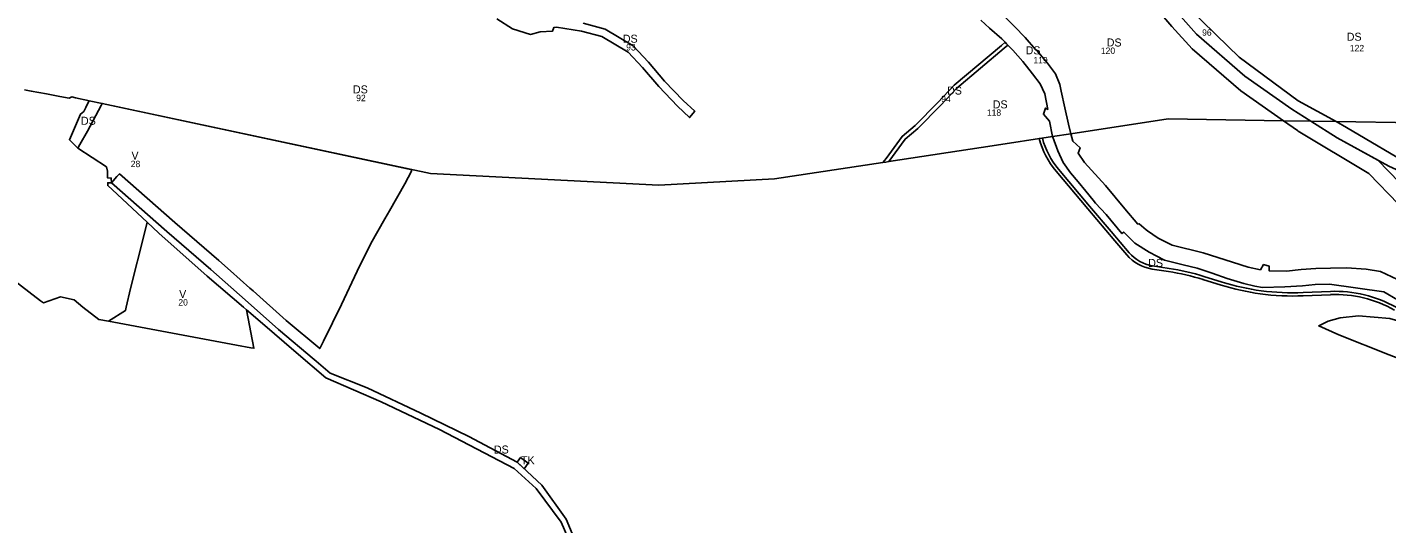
# Model space of a CAD drawing. Extents: x -521621 to -516769, y -1190068 to -1185078.
# Drawn here: x -519528 to -517829, y -1188202 to -1187582 of the extents above; entities that cross this region are included whole.
import ezdxf

# ---------------------------------------------------------------- set-up
doc = ezdxf.new("R2010")
doc.units = 0
for name, color, linetype in [('fpl_id', 7, 'Continuous'), ('v_infrastr_n', 7, 'Continuous'), ('v_infrastr_s', 7, 'Continuous'), ('voda_n', 7, 'Continuous'), ('voda_s', 7, 'Continuous'), ('vyroba_n', 7, 'Continuous'), ('vyroba_s', 7, 'Continuous')]:
    doc.layers.add(name, color=color, linetype=linetype)

msp = doc.modelspace()

# ---------------------------------------------------------------- linework, layer by layer
at = {"layer": 'v_infrastr_n'}
for points in [[(-518142.6, -1187500), (-518125.5, -1187497.4), (-518080.2, -1187553.9), (-518042.1, -1187591.1), (-518013.4, -1187619.1), (-517939.8, -1187673.3), (-517892.4, -1187699.4), (-517923.8, -1187698.9), (-517947.8, -1187683.7), (-518006.3, -1187642.7), (-518067, -1187590.4), (-518102.9, -1187549.4), (-518111.5, -1187538.9), (-518137.5, -1187507.1)], [(-518311.5, -1187525.7), (-518193.2, -1187507.7), (-518188.5, -1187512.3), (-518115.1, -1187560.4), (-518097.5, -1187580.5), (-518072.1, -1187608.7), (-518011.3, -1187661), (-517958.1, -1187698.4), (-518102, -1187696.1), (-518223.7, -1187714.7), (-518226.7, -1187702.5), (-518231.2, -1187682.4), (-518235.9, -1187661.6), (-518237.5, -1187652.9), (-518243.1, -1187639.9), (-518253.1, -1187626.6), (-518266.5, -1187610.8), (-518267.8, -1187609.4), (-518281, -1187594.4), (-518294.1, -1187580.8), (-518310.4, -1187564.3), (-518318.7, -1187557.1), (-518326.5, -1187550.1)], [(-518193.2, -1187507.7), (-518165.5, -1187503.5), (-518111.5, -1187538.9), (-518102.9, -1187549.4), (-518067, -1187590.4), (-518006.3, -1187642.7), (-517947.8, -1187683.7), (-517923.8, -1187698.9), (-517958.1, -1187698.4), (-518011.3, -1187661), (-518072.1, -1187608.7), (-518097.5, -1187580.5), (-518115.1, -1187560.4), (-518188.5, -1187512.3)], [(-518434.6, -1187717.9), (-518418.1, -1187704.4), (-518390.1, -1187675.7), (-518369.6, -1187653.8), (-518310.5, -1187604.3), (-518305.9, -1187600.4), (-518304.1, -1187602.2), (-518302.4, -1187604), (-518307, -1187607.8), (-518366.2, -1187657.5), (-518386.5, -1187679.2), (-518414.8, -1187708.1), (-518430.9, -1187721.3), (-518451.1, -1187749.3), (-518454.9, -1187749.9), (-518458.6, -1187750.5), (-518454.6, -1187745.7), (-518434.6, -1187718)]]:
    msp.add_lwpolyline(points, close=True, dxfattribs=at)
for points in [[(-518125.5, -1187497.4), (-518115.5, -1187495.9), (-517932.8, -1187498.8), (-517912.3, -1187500.7), (-517903.3, -1187502.1), (-517892, -1187510.1), (-517869.1, -1187523.4), (-517829, -1187538.4), (-517785.5, -1187554.6), (-517780, -1187556.7), (-517749.3, -1187570.2), (-517671.4, -1187605.2), (-517631.2, -1187635), (-517621, -1187653.2), (-517598.9, -1187661.5), (-517592.8, -1187665.3), (-517589.2, -1187666.9), (-517596.1, -1187704.1), (-517892.4, -1187699.4)], [(-517892.4, -1187699.4), (-517939.8, -1187673.3), (-518013.4, -1187619.1), (-518042.1, -1187591.1), (-518080.2, -1187553.9), (-518125.5, -1187497.4)], [(-518336.4, -1187572.9), (-518325.6, -1187582.7), (-518310, -1187596), (-518305.9, -1187600.4), (-518310.5, -1187604.3), (-518369.6, -1187653.8), (-518390.1, -1187675.7), (-518418.1, -1187704.4), (-518434.6, -1187717.9), (-518454.6, -1187745.7), (-518458.6, -1187750.5), (-518594.2, -1187771.1), (-518738.7, -1187779), (-519023.8, -1187764.4), (-519433.9, -1187676.7), (-519450.5, -1187673.5), (-519453.5, -1187672.8), (-519458, -1187671.8), (-519461.7, -1187670.9), (-519467.2, -1187669.7), (-519472.1, -1187668.6), (-519475.5, -1187670.1), (-519486.8, -1187668), (-519495.4, -1187666.4), (-519503.6, -1187664.9), (-519513.2, -1187663.1), (-519522.7, -1187661.3), (-519531.3, -1187659.7)], [(-518833.1, -1187576.5), (-518805.7, -1187584), (-518770.6, -1187604.7), (-518751.6, -1187625.3), (-518731.3, -1187649), (-518708, -1187673), (-518693.8, -1187686.5), (-518700.2, -1187694.3), (-518715.1, -1187680.2), (-518738.7, -1187655.7), (-518759, -1187631.9), (-518777, -1187612.5), (-518809.6, -1187593.3), (-518835.2, -1187586.3), (-518866.3, -1187581.6), (-518869.6, -1187581.7), (-518871.3, -1187586.4), (-518887, -1187587.1), (-518898.8, -1187590.5), (-518921.5, -1187583.6), (-518941, -1187571)], [(-518941, -1187571), (-518921.5, -1187583.6), (-518898.8, -1187590.5), (-518887, -1187587.1), (-518871.3, -1187586.4), (-518869.6, -1187581.7), (-518866.3, -1187581.6), (-518835.2, -1187586.3), (-518809.6, -1187593.3), (-518777, -1187612.5), (-518759, -1187631.9), (-518738.7, -1187655.7), (-518715.1, -1187680.2), (-518700.2, -1187694.3), (-518693.8, -1187686.5), (-518708, -1187673), (-518731.3, -1187649), (-518751.6, -1187625.3), (-518770.6, -1187604.7), (-518805.7, -1187584), (-518833.1, -1187576.5)], [(-518294.1, -1187580.8), (-518281, -1187594.4), (-518267.8, -1187609.4), (-518266.5, -1187610.8), (-518253.1, -1187626.6), (-518243.1, -1187639.9), (-518237.5, -1187652.9), (-518235.9, -1187661.6), (-518231.2, -1187682.4), (-518226.7, -1187702.5), (-518223.7, -1187714.7), (-518246.6, -1187718.2), (-518250.4, -1187698.8), (-518258, -1187690.3), (-518255.4, -1187682.6), (-518252.6, -1187684.1), (-518256.3, -1187664.8), (-518262.3, -1187652.3), (-518271.6, -1187639.8), (-518283.6, -1187624.5), (-518296.4, -1187610.4), (-518302.4, -1187604), (-518304.1, -1187602.2), (-518305.9, -1187600.4), (-518310, -1187596), (-518325.6, -1187582.7), (-518336.4, -1187572.9)], [(-518246.6, -1187718.2), (-518322.2, -1187729.7), (-518451.1, -1187749.3), (-518430.9, -1187721.3), (-518414.8, -1187708.1), (-518386.5, -1187679.2), (-518366.2, -1187657.5), (-518307, -1187607.8), (-518302.4, -1187604)], [(-518302.4, -1187604), (-518296.4, -1187610.4), (-518283.6, -1187624.5), (-518271.6, -1187639.8), (-518262.3, -1187652.3), (-518256.3, -1187664.8), (-518252.6, -1187684.1), (-518255.4, -1187682.6), (-518258, -1187690.3), (-518250.4, -1187698.8), (-518246.6, -1187718.2)], [(-517940.8, -1187710.5), (-517958.1, -1187698.4), (-517923.8, -1187698.9), (-517890.9, -1187719.9), (-517840.1, -1187747.4)], [(-517840.1, -1187747.4), (-517799.3, -1187789.7), (-517714, -1187904.5), (-517695.5, -1187912.6), (-517704.3, -1187930.6), (-517726.9, -1187920.7), (-517814.6, -1187802.6), (-517851.6, -1187764.3), (-517939.7, -1187711.3)]]:
    msp.add_lwpolyline(points, dxfattribs=at)
msp.add_arc((-517929.3, -1187694.1), 20, 234.944, 238.9499, dxfattribs=at)
at = {"layer": 'v_infrastr_s'}
for points in [[(-519461.9, -1187728.2), (-519452.6, -1187711.2), (-519435.3, -1187679.3), (-519433.9, -1187676.7), (-519450.5, -1187673.5), (-519452.1, -1187676.6), (-519454.7, -1187681.6), (-519457.2, -1187686.6), (-519461, -1187690.1), (-519475, -1187722), (-519464.3, -1187732.7), (-519461.9, -1187728.2)], [(-517788.7, -1187759.5), (-517793.2, -1187757.7), (-517879.3, -1187706.6), (-517892.4, -1187699.4), (-517923.8, -1187698.9)], [(-517923.8, -1187698.9), (-517890.9, -1187719.9), (-517826.4, -1187754.9), (-517808.2, -1187763.5)], [(-518259.3, -1187720.1), (-518263.2, -1187720.7)], [(-518242.2, -1187761.5), (-518202.5, -1187808.5)], [(-518200.3, -1187804.9), (-518239.2, -1187758.9)], [(-519169.2, -1187996.7), (-519213.9, -1187959.1), (-519255.6, -1187922.2), (-519298.2, -1187884.1), (-519353.1, -1187836.9), (-519422.5, -1187776), (-519425.4, -1187775.9), (-519427.1, -1187775.9), (-519427.1, -1187779.3), (-519421.2, -1187784.7), (-519378, -1187824.9), (-519378, -1187824.9), (-519363.2, -1187838.8), (-519302.7, -1187892.6), (-519257.7, -1187931.2)], [(-518202.5, -1187808.5), (-518168.9, -1187848.2)], [(-518173.4, -1187836.7), (-518200.3, -1187804.9)], [(-518151, -1187863.2), (-518173.4, -1187836.7)], [(-518168.9, -1187848.2), (-518154, -1187865.8)], [(-518122.3, -1187883.6), (-518101.7, -1187886.7)], [(-518101.1, -1187882.8), (-518121.6, -1187879.6)], [(-518058.7, -1187896.7), (-518035.9, -1187903.7)], [(-518034.7, -1187899.9), (-518057.5, -1187892.8)], [(-517899.5, -1187911.6), (-517933.6, -1187913)], [(-517933.5, -1187917), (-517899.3, -1187915.6)], [(-519257.7, -1187931.2), (-519253.8, -1187934.5)], [(-519253.8, -1187934.5), (-519233.6, -1187951.8), (-519191.5, -1187987.8), (-519154.5, -1188019.5), (-519085.5, -1188049.6), (-519012.5, -1188084.1), (-518919.3, -1188132.6), (-518891.7, -1188157.7), (-518860.7, -1188199.6), (-518845.2, -1188235.2)], [(-519166.7, -1187998.8), (-519169.2, -1187996.7)], [(-518838.6, -1188233.7), (-518854.5, -1188196.2), (-518884.6, -1188153.7), (-518915.5, -1188124.9), (-518975.8, -1188092.8), (-519035.8, -1188063.6), (-519102.8, -1188032), (-519149.1, -1188013.6), (-519166.7, -1187998.8)]]:
    msp.add_lwpolyline(points, dxfattribs=at)
msp.add_lwpolyline([(-518915.5, -1188124.9), (-518911.4, -1188118.8), (-518902, -1188126), (-518906.7, -1188133.1)], close=True, dxfattribs=at)
for centre, radius, start, end in [((-518164.4, -1187695.6), 102, 194.2284, 220.234), ((-518164.4, -1187695.6), 98, 194.4563, 220.234), ((-518114.3, -1187832.2), 52, 220.2323, 261.2546), ((-518114.3, -1187832.2), 48, 220.2323, 261.2546), ((-518147, -1188181.3), 298, 72.7538, 81.2533), ((-518147, -1188181.3), 302, 72.7538, 81.2533), ((-517946.4, -1187615.3), 302, 252.7538, 262.2436), ((-517946.4, -1187615.3), 298, 252.7538, 262.3877), ((-517946.4, -1187615.3), 302, 262.2436, 272.4553), ((-517946.4, -1187615.3), 298, 262.3877, 272.4553), ((-517892.9, -1188063.4), 152, 60.2686, 92.4562), ((-517892.9, -1188063.4), 148, 60.2686, 92.4562)]:
    msp.add_arc(centre, radius, start, end, dxfattribs=at)
at = {"layer": 'voda_n'}
msp.add_lwpolyline([(-517864.3, -1187942), (-517825.2, -1187945.2), (-517800.5, -1187952.5), (-517775.2, -1187963.8), (-517753.1, -1187972.8), (-517713, -1187994.8), (-517667, -1188027.7), (-517653.8, -1188036), (-517654.4, -1188038.4), (-517656, -1188041), (-517667.8, -1188038.9), (-517705.4, -1188027.8), (-517779.6, -1188008.6), (-517826.1, -1187990.9), (-517888.9, -1187965.6), (-517914, -1187954.7), (-517902.2, -1187948.9), (-517887.2, -1187944.5)], close=True, dxfattribs=at)
at = {"layer": 'voda_s'}
for points in [[(-518129.6, -1187834.7), (-518138.5, -1187827.1), (-518140.1, -1187827.4), (-518156.2, -1187808.2), (-518180.6, -1187779.3), (-518206.7, -1187750.6), (-518214.8, -1187738.7), (-518212.1, -1187732.3), (-518221.4, -1187724), (-518223.7, -1187714.7), (-518246.6, -1187718.2)], [(-518246.6, -1187718.2), (-518246.4, -1187718.8), (-518239.9, -1187736), (-518233.5, -1187750.6), (-518224.4, -1187763.4), (-518214.8, -1187774.7), (-518205.2, -1187786.3), (-518195.8, -1187797.6), (-518192.9, -1187801.1), (-518179.6, -1187815.4), (-518160, -1187839.2), (-518157.7, -1187837.5), (-518154.7, -1187840.5)], [(-517707.4, -1187945.2), (-517723.6, -1187933.3), (-517746.3, -1187922.6), (-517771, -1187915.8), (-517792.3, -1187908.1), (-517815.6, -1187896.7), (-517836.9, -1187886.7), (-517855, -1187883.6), (-517879.5, -1187882.2), (-517899.4, -1187882.5), (-517917.8, -1187883), (-517936, -1187884), (-517954.2, -1187886.1), (-517976, -1187885.9), (-517976, -1187880.1), (-517982.9, -1187878.1), (-517987, -1187884.5), (-518002.4, -1187881.3), (-518021.9, -1187875.1), (-518058.6, -1187863.4), (-518097.1, -1187853.8), (-518114.6, -1187845), (-518128.2, -1187835.9), (-518129.6, -1187834.7)], [(-518154.7, -1187840.5), (-518144, -1187851.1), (-518126, -1187862.7), (-518106.7, -1187872.3), (-518083.3, -1187878.4), (-518066.1, -1187882.6), (-518047.3, -1187888.6), (-518028.5, -1187895.2), (-518007.8, -1187901.8), (-517994.1, -1187904.8), (-517984.5, -1187906.5), (-517956.5, -1187905.8), (-517934.3, -1187904.6), (-517918.4, -1187902.9), (-517900.6, -1187902.6), (-517832.6, -1187912), (-517815.8, -1187921.9)]]:
    msp.add_lwpolyline(points, dxfattribs=at)
at = {"layer": 'vyroba_n'}
for points in [[(-519273.6, -1187886), (-519288.3, -1187872.8), (-519343.3, -1187825.6), (-519412.6, -1187764.7), (-519415.6, -1187768.2), (-519422.5, -1187776), (-519422.8, -1187770), (-519427.3, -1187769.8), (-519427.6, -1187761.4), (-519428, -1187759.6), (-519428.8, -1187756.1), (-519464.3, -1187732.7), (-519461.9, -1187728.2), (-519452.6, -1187711.2), (-519435.3, -1187679.3), (-519433.9, -1187676.7), (-519046.8, -1187759.5)], [(-519047.4, -1187760.7), (-519047.8, -1187761.5), (-519056, -1187777), (-519075.2, -1187811), (-519080.8, -1187821), (-519098.4, -1187851.5), (-519115.5, -1187886.4), (-519135.2, -1187927.9), (-519157.4, -1187973.7), (-519162.2, -1187983), (-519204.1, -1187947.8), (-519245.6, -1187911), (-519249.5, -1187907.6)], [(-519046.8, -1187759.5), (-519047.4, -1187760.7)], [(-519249.5, -1187907.6), (-519273.6, -1187886)]]:
    msp.add_lwpolyline(points, dxfattribs=at)
msp.add_lwpolyline([(-519266.2, -1187978.5), (-519426, -1187948.6), (-519405, -1187935.4), (-519404.2, -1187931.3), (-519398.5, -1187907.9), (-519381.7, -1187840.3), (-519378, -1187824.9), (-519363.2, -1187838.8), (-519302.7, -1187892.6), (-519257.7, -1187931.2), (-519253.8, -1187934.5), (-519244.5, -1187982.5), (-519248.2, -1187981.9)], close=True, dxfattribs=at)
at = {"layer": 'vyroba_s'}
for p, q in [((-519427.6, -1187761.4), (-519427.3, -1187769.8)), ((-519427.3, -1187769.8), (-519422.8, -1187770)), ((-519425.4, -1187775.9), (-519427.1, -1187775.9)), ((-519427.1, -1187775.9), (-519427.1, -1187779.3))]:
    msp.add_line(p, q, dxfattribs=at)
for points in [[(-519531.3, -1187659.7), (-519522.7, -1187661.3), (-519513.2, -1187663.1), (-519503.6, -1187664.9), (-519495.4, -1187666.4), (-519486.8, -1187668), (-519475.5, -1187670.1), (-519472.1, -1187668.6), (-519467.2, -1187669.7), (-519461.7, -1187670.9), (-519458, -1187671.8), (-519453.5, -1187672.8), (-519450.5, -1187673.5), (-519452.1, -1187676.6), (-519454.7, -1187681.6), (-519457.2, -1187686.6), (-519461, -1187690.1), (-519475, -1187722), (-519464.3, -1187732.7), (-519428.8, -1187756.1), (-519427.6, -1187761.4)], [(-519427.1, -1187779.3), (-519421.2, -1187784.7), (-519378, -1187824.9), (-519381.7, -1187840.3), (-519398.5, -1187907.9), (-519404.2, -1187931.3), (-519404.2, -1187931.3), (-519405, -1187935.4), (-519426, -1187948.6), (-519438.3, -1187946.8), (-519458.1, -1187931.2), (-519469.2, -1187922.2), (-519486.2, -1187918.1), (-519507.4, -1187926), (-519511, -1187923.3), (-519549.5, -1187893.8)], [(-519422.8, -1187770), (-519422.5, -1187776), (-519425.4, -1187775.9)]]:
    msp.add_lwpolyline(points, dxfattribs=at)

# ---------------------------------------------------------------- texts
at = {"layer": 'fpl_id'}
for s, p in [('96', (-518059.8, -1187592.2)), ('93', (-518779.4, -1187610.6)), ('120', (-518186.3, -1187614.9)), ('122', (-517875.2, -1187611.6)), ('119', (-518270.6, -1187626.7)), ('92', (-519116.7, -1187673.9)), ('94', (-518385.8, -1187675)), ('118', (-518328.7, -1187692.2)), ('28', (-519398.4, -1187756.3)), ('20', (-519338.9, -1187929.2))]:
    msp.add_text(s, height=8, dxfattribs=at).set_placement(p)
at = {"layer": 'v_infrastr_n'}
for p in [(-518783.6, -1187600.9), (-518179, -1187605.6), (-517879.1, -1187598.4), (-518280.3, -1187615.4), (-519120.8, -1187664.2), (-518378.5, -1187665.6), (-518321.4, -1187682.9)]:
    msp.add_text('DS', height=10, dxfattribs=at).set_placement(p)
at = {"layer": 'v_infrastr_s'}
for s, p in [('DS', (-519460.6, -1187703.4)), ('DS', (-518127.2, -1187880.9)), ('DS', (-518944.7, -1188114)), ('TK', (-518910.8, -1188127.4))]:
    msp.add_text(s, height=10, dxfattribs=at).set_placement(p)
at = {"layer": 'vyroba_n'}
for p in [(-519397.5, -1187746.8), (-519337.9, -1187919.7)]:
    msp.add_text('V', height=10, dxfattribs=at).set_placement(p)

doc.saveas('drawing.dxf')
